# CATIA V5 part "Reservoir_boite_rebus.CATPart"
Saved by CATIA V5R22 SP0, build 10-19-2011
Part number: Reservoir_boite_rebus
Bounding box of the stored display mesh (mm): x 0 to 120, y 0 to 140, z 0 to 200
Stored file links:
  C:\Users\La forge\Desktop\CAO_PER_pick&place_2023A\Sous_Ensemble_Boite\Reservoir_Boite\Reservoir_boite_rebus.CATPart
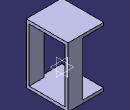
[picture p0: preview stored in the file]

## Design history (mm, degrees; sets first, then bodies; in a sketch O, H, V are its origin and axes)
Body1 (main body)
  Sketch1 on yz-plane, origin (0, 0, 0), H (0, 1, 0), V (0, 0, 1)
    line L1 (0, 0) -> (140, 0)
    line L2 (140, 0) -> (140, 200)
    line L3 (140, 200) -> (0, 200)
    line L4 (0, 200) -> (0, 0)
    point P1 (140, 0)
    point P2 (140, 200)
    point P3 (0, 200)
    distance P3 P2 = 140
    distance P2 P1 = 200
    horizontal: L1 H, L3 H
    vertical: L2 V, L4 V
  Pad1: profile Sketch1, direction (1, 0, 0), length 120
  Sketch2 on face of Pad1 from Sketch1.L4, origin (0, 0, 0), H (1, 0, 0), V (0, 0, 1)
    point P1 (0, 10)
    line L1 (0, 10) -> (70, 10)
    line L2 (70, 10) -> (70, 190)
    line L3 (70, 190) -> (0, 190)
    line L4 (0, 190) -> (0, 10)
    point P2 (70, 10)
    point P4 (0, 190)
    reference projected point E1 (0, 200) from vertex [face of Pad1 from Sketch1.L4 | start face of Pad1 | face of Pad1 from Sketch1.L3]
    distance P1 O = 10
    distance E1 P4 = 10
    distance P2 P1 = 70
    coincidence: P1 V
    horizontal: L1 H, L3 H
    vertical: L2 V, L4 V
  Pocket1: profile Sketch2, direction (0, 1, 0), through (limit type 3)
  Sketch3 on end face of Pad1, origin (120, 0, 0), H (0, 1, 0), V (0, 0, 1)
    point P1 (10, 10)
    line L1 (10, 10) -> (130, 10)
    line L2 (130, 10) -> (130, 190)
    line L3 (130, 190) -> (10, 190)
    line L4 (10, 190) -> (10, 10)
    point P3 (130, 190)
    point P4 (10, 190)
    reference projected line E1 (140, 200) -> (0, 200) from edge [face of Pad1 from Sketch1.L3 | end face of Pad1]
    reference projected line E2 (140, 0) -> (140, 200) from edge [face of Pad1 from Sketch1.L2 | end face of Pad1]
    reference projected line E3 (0, 0) -> (140, 0) from edge [face of Pad1 from Sketch1.L1 | end face of Pad1]
    reference projected line E4 (0, 200) -> (0, 0) from edge [face of Pad1 from Sketch1.L4 | end face of Pad1]
    distance P3 E1 = 10
    distance P3 E2 = 10
    distance P1 E3 = 10
    distance P4 E4 = 10
    horizontal: L1 H, L3 H
    vertical: L2 V, L4 V
  Pocket2: profile Sketch3, direction (-1, 0, 0), through (limit type 3)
